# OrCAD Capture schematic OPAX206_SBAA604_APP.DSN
size A; title: Bipolar to Unipolar Level Translation with Buffer; rev: 1.0; company: Texas Instruments Inc.; note: Datasheet: SBOSA11D  Reference Doc: SBAA604
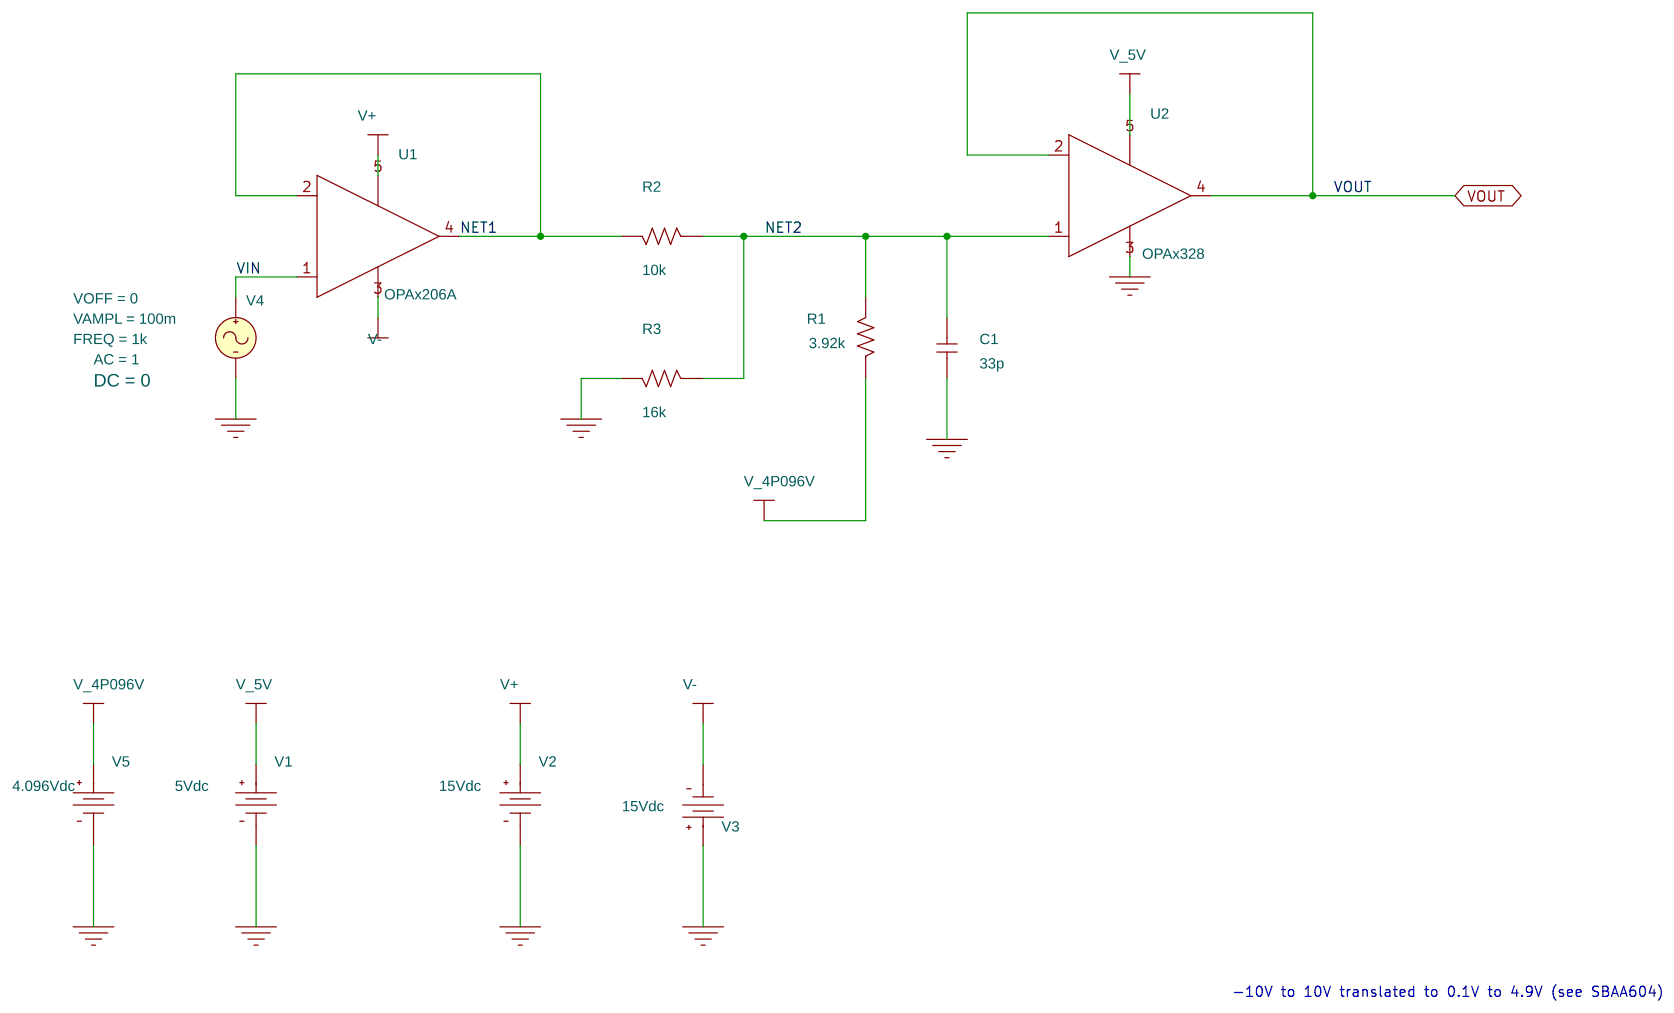
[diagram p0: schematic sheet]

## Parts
C1  33p  [cap196]
R1  3.92k  [AXRC05]
R2  10k  [AXRC05]
R3  16k  [AXRC05]
U1  OPAx206A
U2  OPAx328
V1  VDC
V2  VDC
V3  VDC
V4  VSIN
V5  VDC

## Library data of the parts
C1 = C: IC: 0
R1-R3 = R
U1 = OPAx206A: Testbenches: [{"testbenchurl":"https://software-dl.ti.com/pspice/esd/models/OPAx206A_V2.0.zip","testbenchopj":"OPAx206A_Test_Circuit.OPJ","testbenchdisplayname":"OPAx206A PSpice Model"}]; productURL: http://www.ti.com/document-viewer/OPA2206/datasheet/
U2 = OPAx328: Testbenches: [{"testbenchurl":"https://software-dl.ti.com/pspice/esd/models/OPAx328_V2.0.zip","testbenchopj":"OPAx328_Test_Circuit.OPJ","testbenchdisplayname":"OPAx328 PSpice Model"}]; productURL: http://www.ti.com/document-viewer/OPA2328/datasheet/
V1 = VDC: DC: 5Vdc
V2 V3 = VDC: DC: 15Vdc
V4 = VSIN: AC: 1; AppProp: Sine$Voltage$0$-1; DC: 0; FREQ: 1k; VAMPL: 100m; VOFF: 0
V5 = VDC: DC: 4.096Vdc

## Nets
VIN: U1.1(+) V4.1(+)
0: C1.1 R3.2 U2.3(V-) V1.1(-) V2.1(-) V3.0(+) V4.2(-) V5.1(-)
NET1: R2.2 U1.2(-) U1.4(OUT)
NET2: C1.2 R1.2 R2.1 R3.1 U2.1(+)
V+: U1.5(V+) V2.0(+)
V-: U1.3(V-) V3.1(-)
V_4p096V: R1.1 V5.0(+)
V_5V: U2.5(V+) V1.0(+)
VOUT: U2.2(-) U2.4(OUT)

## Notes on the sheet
- -10V to 10V translated to 0.1V to 4.9V (see SBAA604)
